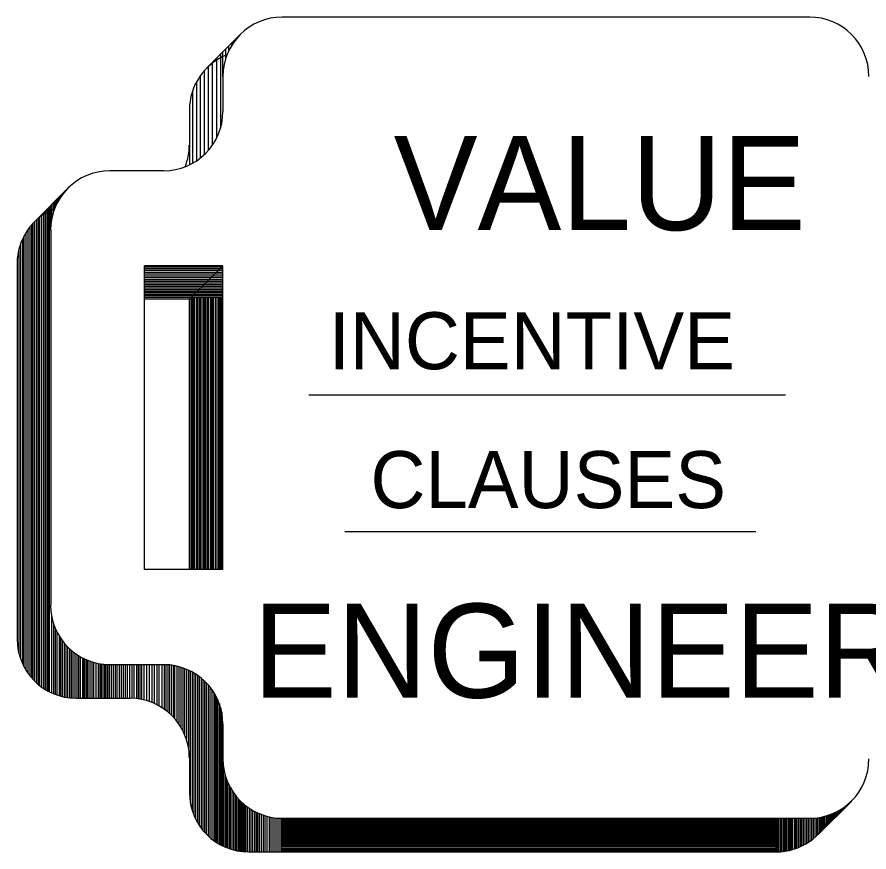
# Model space of a CAD drawing. Extents: x 22339.2 to 22413.4, y 22369.6 to 22418.8.
# Drawn here: x 22357.866 to 22359.063, y 22371.331 to 22372.503 of the extents above; entities that cross this region are included whole.
import ezdxf

# ---------------------------------------------------------------- set-up
doc = ezdxf.new("R2010")
doc.units = 0
doc.layers.add('Level 2', color=7, linetype='Continuous')
doc.layers.add('Level 7', color=7, linetype='Continuous')

msp = doc.modelspace()

# ---------------------------------------------------------------- linework, layer by layer
at = {"layer": 'Level 2'}
for p, q in [((22358.1327, 22372.432), (22358.1799, 22372.4792)), ((22358.1681, 22372.464), (22358.1681, 22372.4673)), ((22358.1716, 22372.4693), (22358.1716, 22372.4708)), ((22358.1556, 22372.4202), (22358.1556, 22372.4548)), ((22358.1596, 22372.4457), (22358.1596, 22372.4588)), ((22358.1639, 22372.4565), (22358.1639, 22372.4632)), ((22358.1466, 22372.4458), (22358.1466, 22372.3333)), ((22358.1522, 22372.4515), (22358.1522, 22372.3477)), ((22358.1349, 22372.4342), (22358.1349, 22372.316)), ((22358.1406, 22372.4398), (22358.1406, 22372.3233)), ((22358.1237, 22372.4212), (22358.1237, 22372.3055)), ((22358.1294, 22372.4283), (22358.1294, 22372.3103)), ((22358.1186, 22372.4128), (22358.1186, 22372.3017)), ((22358.1129, 22372.4), (22358.1129, 22372.2983)), ((22358.1084, 22372.373), (22358.1084, 22372.296)), ((22357.8907, 22372.2162), (22357.9379, 22372.2633)), ((22357.9244, 22372.2455), (22357.9244, 22372.2498)), ((22357.9261, 22372.2482), (22357.9261, 22372.2515)), ((22357.9277, 22372.2508), (22357.9277, 22372.2532)), ((22357.9294, 22372.2532), (22357.9294, 22372.2548)), ((22357.9117, 22372.2372), (22357.9117, 22371.5563)), ((22357.9136, 22372.2043), (22357.9136, 22372.239)), ((22357.9154, 22372.2217), (22357.9154, 22372.2408)), ((22357.9177, 22372.2303), (22357.9177, 22372.2432)), ((22357.9196, 22372.2353), (22357.9196, 22372.245)), ((22357.9212, 22372.2392), (22357.9212, 22372.2467)), ((22357.9227, 22372.2423), (22357.9227, 22372.2482)), ((22357.9007, 22372.2262), (22357.9007, 22371.5632)), ((22357.9036, 22372.229), (22357.9036, 22371.5612)), ((22357.9059, 22372.2313), (22357.9059, 22371.5597)), ((22357.9081, 22372.2335), (22357.9081, 22371.5583)), ((22357.9102, 22372.2357), (22357.9102, 22371.5572)), ((22357.8887, 22372.214), (22357.8887, 22371.5737)), ((22357.8911, 22372.2163), (22357.8911, 22371.5713)), ((22357.8939, 22372.2193), (22357.8939, 22371.5687)), ((22357.8959, 22372.2213), (22357.8959, 22371.5668)), ((22357.8981, 22372.2235), (22357.8981, 22371.5652)), ((22357.8814, 22372.2048), (22357.8814, 22371.5828)), ((22357.8842, 22372.2087), (22357.8842, 22371.579)), ((22357.8866, 22372.2115), (22357.8866, 22371.5762)), ((22357.8739, 22372.1917), (22357.8739, 22371.596)), ((22357.8761, 22372.1962), (22357.8761, 22371.5915)), ((22357.8787, 22372.2008), (22357.8787, 22371.5868)), ((22357.8712, 22372.1852), (22357.8712, 22371.6025)), ((22357.8687, 22372.1767), (22357.8687, 22371.611)), ((22357.8664, 22372.1572), (22357.8664, 22371.6305)), ((22358.1556, 22372.1543), (22358.1084, 22372.1072)), ((22358.1556, 22372.1522), (22358.0452, 22372.1522)), ((22358.1556, 22372.15), (22358.0452, 22372.15)), ((22358.1556, 22372.1475), (22358.0452, 22372.1475)), ((22358.1556, 22372.145), (22358.0452, 22372.145)), ((22358.1556, 22372.1423), (22358.0452, 22372.1423)), ((22358.1556, 22372.1398), (22358.0452, 22372.1398)), ((22358.1556, 22372.1373), (22358.0452, 22372.1373)), ((22358.1556, 22372.1347), (22358.0452, 22372.1347)), ((22358.1556, 22372.1323), (22358.0452, 22372.1323)), ((22358.1556, 22372.1298), (22358.0452, 22372.1298)), ((22358.1556, 22372.1273), (22358.0452, 22372.1273)), ((22358.1556, 22372.125), (22358.0452, 22372.125)), ((22358.1556, 22372.1227), (22358.0452, 22372.1227)), ((22358.1556, 22372.1207), (22358.0452, 22372.1207)), ((22358.1556, 22372.1182), (22358.0452, 22372.1182)), ((22358.1556, 22372.1162), (22358.0452, 22372.1162)), ((22358.1556, 22372.114), (22358.0452, 22372.114)), ((22358.1556, 22372.112), (22358.0452, 22372.112)), ((22358.1556, 22372.1095), (22358.0452, 22372.1095)), ((22358.1084, 22372.1072), (22358.0452, 22372.1072)), ((22358.1084, 22371.7277), (22358.1084, 22372.1072)), ((22358.1107, 22371.7277), (22358.1107, 22372.1095)), ((22358.1126, 22371.7277), (22358.1126, 22372.1095)), ((22358.1146, 22371.7277), (22358.1146, 22372.1095)), ((22358.1162, 22371.7277), (22358.1162, 22372.1095)), ((22358.1187, 22371.7277), (22358.1187, 22372.1095)), ((22358.1209, 22371.7277), (22358.1209, 22372.1095)), ((22358.1232, 22371.7277), (22358.1232, 22372.1095)), ((22358.1249, 22371.7277), (22358.1249, 22372.1095)), ((22358.1276, 22371.7277), (22358.1276, 22372.1095)), ((22358.1297, 22371.7277), (22358.1297, 22372.1095)), ((22358.1316, 22371.7277), (22358.1316, 22372.1095)), ((22358.1337, 22371.7277), (22358.1337, 22372.1095)), ((22358.1359, 22371.7277), (22358.1359, 22372.1095)), ((22358.1384, 22371.7277), (22358.1384, 22372.1095)), ((22358.1404, 22371.7277), (22358.1404, 22372.1095)), ((22358.1424, 22371.7277), (22358.1424, 22372.1095)), ((22358.1449, 22371.7277), (22358.1449, 22372.1095)), ((22358.1474, 22371.7277), (22358.1474, 22372.1095)), ((22358.1499, 22371.7277), (22358.1499, 22372.1095)), ((22358.1516, 22371.7277), (22358.1516, 22372.1095)), ((22358.1537, 22371.7277), (22358.1537, 22372.1095)), ((22357.9147, 22371.6638), (22357.9147, 22371.5548)), ((22357.9174, 22371.6527), (22357.9174, 22371.5537)), ((22357.9199, 22371.6458), (22357.9199, 22371.5527)), ((22357.9224, 22371.6403), (22357.9224, 22371.5518)), ((22357.9254, 22371.6348), (22357.9254, 22371.5508)), ((22357.9276, 22371.6315), (22357.9276, 22371.5502)), ((22357.9297, 22371.6283), (22357.9297, 22371.5497)), ((22357.9326, 22371.6247), (22357.9326, 22371.549)), ((22357.9349, 22371.622), (22357.9349, 22371.5485)), ((22357.9374, 22371.6193), (22357.9374, 22371.5482)), ((22357.9399, 22371.6168), (22357.9399, 22371.5477)), ((22357.9424, 22371.6147), (22357.9424, 22371.5475)), ((22357.9447, 22371.6127), (22357.9447, 22371.5473)), ((22357.9476, 22371.6105), (22357.9476, 22371.5472)), ((22357.9501, 22371.6087), (22357.9501, 22371.5472)), ((22357.9526, 22371.6072), (22357.9526, 22371.5472)), ((22357.9551, 22371.6057), (22357.9551, 22371.5472)), ((22357.9581, 22371.604), (22357.9581, 22371.5472)), ((22357.9602, 22371.6028), (22357.9602, 22371.5472)), ((22357.9616, 22371.6022), (22357.9616, 22371.5472)), ((22357.9637, 22371.6012), (22357.9637, 22371.5472)), ((22357.9659, 22371.6003), (22357.9659, 22371.5472)), ((22357.9686, 22371.5993), (22357.9686, 22371.5472)), ((22357.9712, 22371.5983), (22357.9712, 22371.5472)), ((22357.9737, 22371.5977), (22357.9737, 22371.5472)), ((22357.9771, 22371.5967), (22357.9771, 22371.5472)), ((22357.9801, 22371.596), (22357.9801, 22371.5472)), ((22357.9826, 22371.5955), (22357.9826, 22371.5472)), ((22357.9844, 22371.5953), (22357.9844, 22371.5472)), ((22357.9869, 22371.595), (22357.9869, 22371.5472)), ((22357.9891, 22371.5947), (22357.9891, 22371.5472)), ((22357.9909, 22371.5945), (22357.9909, 22371.5472)), ((22357.9932, 22371.5943), (22357.9932, 22371.5472)), ((22357.9959, 22371.5943), (22357.9959, 22371.5472)), ((22357.9984, 22371.5943), (22357.9984, 22371.5472)), ((22358.0012, 22371.5943), (22358.0012, 22371.5472)), ((22358.0041, 22371.5943), (22358.0041, 22371.5472)), ((22358.0066, 22371.5943), (22358.0066, 22371.5472)), ((22358.0099, 22371.5943), (22358.0099, 22371.5472)), ((22358.0127, 22371.5943), (22358.0127, 22371.5472)), ((22358.0152, 22371.5943), (22358.0152, 22371.5472)), ((22358.0181, 22371.5943), (22358.0181, 22371.5472)), ((22358.0212, 22371.5943), (22358.0212, 22371.5472)), ((22358.0242, 22371.5943), (22358.0242, 22371.5472)), ((22358.0274, 22371.5943), (22358.0274, 22371.5472)), ((22358.0306, 22371.5943), (22358.0306, 22371.5472)), ((22358.0342, 22371.5943), (22358.0342, 22371.5467)), ((22358.0367, 22371.5943), (22358.0367, 22371.5463)), ((22358.0389, 22371.5943), (22358.0389, 22371.546)), ((22358.0411, 22371.5943), (22358.0411, 22371.5457)), ((22358.0446, 22371.5943), (22358.0446, 22371.5448)), ((22358.0482, 22371.5943), (22358.0482, 22371.5438)), ((22358.0521, 22371.5943), (22358.0521, 22371.5427)), ((22358.0557, 22371.5943), (22358.0557, 22371.5413)), ((22358.0589, 22371.5943), (22358.0589, 22371.54)), ((22358.0626, 22371.5943), (22358.0626, 22371.5383)), ((22358.0654, 22371.5943), (22358.0654, 22371.5368)), ((22358.0697, 22371.5943), (22358.0697, 22371.5342)), ((22358.0732, 22371.5943), (22358.0732, 22371.5318)), ((22358.0751, 22371.5943), (22358.0751, 22371.5305)), ((22358.0782, 22371.5943), (22358.0782, 22371.528)), ((22358.0807, 22371.5938), (22358.0807, 22371.5258)), ((22358.0834, 22371.5935), (22358.0834, 22371.5233)), ((22358.0859, 22371.5932), (22358.0859, 22371.5208)), ((22358.0877, 22371.5928), (22358.0877, 22371.5188)), ((22358.0906, 22371.5923), (22358.0906, 22371.5153)), ((22358.0934, 22371.5917), (22358.0934, 22371.5115)), ((22358.0964, 22371.5908), (22358.0964, 22371.5068)), ((22358.0992, 22371.5898), (22358.0992, 22371.5018)), ((22358.1017, 22371.589), (22358.1017, 22371.4965)), ((22358.1044, 22371.5878), (22358.1044, 22371.4893)), ((22358.1072, 22371.5867), (22358.1072, 22371.4777)), ((22358.1094, 22371.5857), (22358.1094, 22371.4018)), ((22358.1121, 22371.5842), (22358.1121, 22371.3902)), ((22358.1147, 22371.5827), (22358.1147, 22371.3828)), ((22358.1172, 22371.5812), (22358.1172, 22371.3773)), ((22358.1197, 22371.5795), (22358.1197, 22371.3727)), ((22358.1222, 22371.5777), (22358.1222, 22371.3687)), ((22358.1251, 22371.5755), (22358.1251, 22371.3647)), ((22358.1272, 22371.5737), (22358.1272, 22371.3618)), ((22358.1297, 22371.5713), (22358.1297, 22371.359)), ((22358.1319, 22371.5692), (22358.1319, 22371.3567)), ((22358.1346, 22371.5663), (22358.1346, 22371.354)), ((22358.1371, 22371.5633), (22358.1371, 22371.3518)), ((22358.1399, 22371.5597), (22358.1399, 22371.3493)), ((22358.1426, 22371.5557), (22358.1426, 22371.3473)), ((22357.9497, 22371.5472), (22358.0251, 22371.5472)), ((22358.1447, 22371.5522), (22358.1447, 22371.3458)), ((22358.1467, 22371.5483), (22358.1467, 22371.3445)), ((22358.1484, 22371.5448), (22358.1484, 22371.3435)), ((22358.1506, 22371.5395), (22358.1506, 22371.3422)), ((22358.1524, 22371.5338), (22358.1524, 22371.3412)), ((22358.1539, 22371.5275), (22358.1539, 22371.3403)), ((22358.1084, 22371.4638), (22358.1084, 22371.4147)), ((22358.1557, 22371.4565), (22358.1557, 22371.3395)), ((22358.1581, 22371.4415), (22358.1581, 22371.3385)), ((22358.1602, 22371.4343), (22358.1602, 22371.3375)), ((22358.1621, 22371.4295), (22358.1621, 22371.3368)), ((22358.1641, 22371.4252), (22358.1641, 22371.336)), ((22358.1657, 22371.422), (22358.1657, 22371.3355)), ((22358.1681, 22371.418), (22358.1681, 22371.3348)), ((22358.1702, 22371.4147), (22358.1702, 22371.3342)), ((22358.1726, 22371.4113), (22358.1726, 22371.3335)), ((22358.1742, 22371.4093), (22358.1742, 22371.3332)), ((22358.1766, 22371.4065), (22358.1766, 22371.3327)), ((22358.1779, 22371.405), (22358.1779, 22371.3325)), ((22358.1797, 22371.4032), (22358.1797, 22371.3322)), ((22358.1817, 22371.4012), (22358.1817, 22371.332)), ((22358.1832, 22371.3998), (22358.1832, 22371.3318)), ((22358.9914, 22371.3557), (22359.0386, 22371.4028)), ((22358.1842, 22371.399), (22358.1842, 22371.3317)), ((22358.1854, 22371.398), (22358.1854, 22371.3315)), ((22358.1872, 22371.3965), (22358.1872, 22371.3315)), ((22358.1896, 22371.3947), (22358.1896, 22371.3315)), ((22358.1922, 22371.3928), (22358.1922, 22371.3315)), ((22358.1946, 22371.3913), (22358.1946, 22371.3315)), ((22358.1972, 22371.3897), (22358.1972, 22371.3315)), ((22358.1997, 22371.3883), (22358.1997, 22371.3315)), ((22359.0187, 22371.383), (22359.0187, 22371.3883)), ((22359.0202, 22371.3845), (22359.0202, 22371.3892)), ((22359.0217, 22371.386), (22359.0217, 22371.39)), ((22359.0234, 22371.3877), (22359.0234, 22371.391)), ((22359.0251, 22371.3893), (22359.0251, 22371.392)), ((22359.0266, 22371.3908), (22359.0266, 22371.393)), ((22359.0281, 22371.3923), (22359.0281, 22371.394)), ((22359.0296, 22371.3938), (22359.0296, 22371.3952)), ((22358.2022, 22371.387), (22358.2022, 22371.3315)), ((22358.2042, 22371.386), (22358.2042, 22371.3315)), ((22358.2066, 22371.385), (22358.2066, 22371.3315)), ((22358.2092, 22371.384), (22358.2092, 22371.3315)), ((22358.2119, 22371.383), (22358.2119, 22371.3315)), ((22358.2146, 22371.3822), (22358.2146, 22371.3315)), ((22358.2174, 22371.3813), (22358.2174, 22371.3315)), ((22358.2204, 22371.3805), (22358.2204, 22371.3315)), ((22358.2227, 22371.38), (22358.2227, 22371.3315)), ((22358.2257, 22371.3795), (22358.2257, 22371.3315)), ((22358.2284, 22371.3792), (22358.2284, 22371.3315)), ((22358.2311, 22371.3788), (22358.2311, 22371.3315)), ((22358.2342, 22371.3787), (22358.2342, 22371.3315)), ((22358.2369, 22371.3785), (22358.2369, 22371.3315)), ((22358.2369, 22371.3773), (22358.9324, 22371.3773)), ((22358.2369, 22371.3765), (22358.9324, 22371.3765)), ((22358.2369, 22371.3757), (22358.9324, 22371.3757)), ((22358.9324, 22371.3313), (22358.9324, 22371.3785)), ((22358.9342, 22371.3313), (22358.9342, 22371.3785)), ((22358.9356, 22371.3313), (22358.9356, 22371.3785)), ((22358.9369, 22371.3315), (22358.9369, 22371.3785)), ((22358.9391, 22371.3317), (22358.9391, 22371.3785)), ((22358.9407, 22371.3318), (22358.9407, 22371.3785)), ((22358.9427, 22371.332), (22358.9427, 22371.3785)), ((22358.9444, 22371.3322), (22358.9444, 22371.3785)), ((22358.9462, 22371.3325), (22358.9462, 22371.3785)), ((22358.9477, 22371.3328), (22358.9477, 22371.3785)), ((22358.9497, 22371.3332), (22358.9497, 22371.3785)), ((22358.9516, 22371.3335), (22358.9516, 22371.3785)), ((22358.9534, 22371.334), (22358.9534, 22371.3785)), ((22358.9557, 22371.3347), (22358.9557, 22371.3785)), ((22358.9582, 22371.3355), (22358.9582, 22371.3785)), ((22358.9602, 22371.3362), (22358.9602, 22371.3785)), ((22358.9622, 22371.3368), (22358.9622, 22371.3785)), ((22358.9644, 22371.3377), (22358.9644, 22371.3785)), ((22358.9666, 22371.3387), (22358.9666, 22371.3785)), ((22358.9684, 22371.3395), (22358.9684, 22371.3785)), ((22358.9709, 22371.3408), (22358.9709, 22371.3785)), ((22358.9734, 22371.3422), (22358.9734, 22371.3785)), ((22358.9757, 22371.3435), (22358.9757, 22371.3785)), ((22358.9781, 22371.345), (22358.9781, 22371.3785)), ((22358.9804, 22371.3465), (22358.9804, 22371.3785)), ((22358.9826, 22371.3482), (22358.9826, 22371.3785)), ((22358.9849, 22371.35), (22358.9849, 22371.3785)), ((22358.9874, 22371.352), (22358.9874, 22371.3788)), ((22358.9897, 22371.3542), (22358.9897, 22371.3792)), ((22358.9917, 22371.356), (22358.9917, 22371.3793)), ((22358.9939, 22371.3582), (22358.9939, 22371.3797)), ((22358.9956, 22371.3598), (22358.9956, 22371.38)), ((22358.9976, 22371.3618), (22358.9976, 22371.3805)), ((22358.9992, 22371.3635), (22358.9992, 22371.3808)), ((22359.0011, 22371.3653), (22359.0011, 22371.3813)), ((22359.0031, 22371.3673), (22359.0031, 22371.3818)), ((22359.0044, 22371.3687), (22359.0044, 22371.3823)), ((22359.0061, 22371.3703), (22359.0061, 22371.3828)), ((22359.0076, 22371.3718), (22359.0076, 22371.3833)), ((22359.0092, 22371.3735), (22359.0092, 22371.384)), ((22359.0102, 22371.3745), (22359.0102, 22371.3843)), ((22359.0122, 22371.3765), (22359.0122, 22371.3852)), ((22359.0137, 22371.378), (22359.0137, 22371.3858)), ((22359.0154, 22371.3797), (22359.0154, 22371.3867)), ((22359.0172, 22371.3815), (22359.0172, 22371.3875)), ((22358.2369, 22371.3745), (22358.9324, 22371.3745)), ((22358.2369, 22371.3732), (22358.9324, 22371.3732)), ((22358.2369, 22371.3717), (22358.9324, 22371.3717)), ((22358.2369, 22371.3702), (22358.9324, 22371.3702)), ((22358.2369, 22371.3688), (22358.9324, 22371.3688)), ((22358.2369, 22371.3673), (22358.9324, 22371.3673)), ((22358.2369, 22371.3658), (22358.9324, 22371.3658)), ((22358.2369, 22371.3643), (22358.9324, 22371.3643)), ((22358.2369, 22371.3628), (22358.9324, 22371.3628)), ((22358.2369, 22371.3613), (22358.9324, 22371.3613)), ((22358.2369, 22371.36), (22358.9324, 22371.36)), ((22358.2369, 22371.3585), (22358.9324, 22371.3585)), ((22358.2369, 22371.3572), (22358.9324, 22371.3572)), ((22358.2369, 22371.3558), (22358.9324, 22371.3558)), ((22358.2369, 22371.3543), (22358.9324, 22371.3543)), ((22358.2369, 22371.3528), (22358.9324, 22371.3528)), ((22358.2369, 22371.3512), (22358.9324, 22371.3512)), ((22358.2369, 22371.3495), (22358.9324, 22371.3495)), ((22358.2369, 22371.3478), (22358.9324, 22371.3478)), ((22358.2369, 22371.3463), (22358.9324, 22371.3463)), ((22358.2369, 22371.3445), (22358.9324, 22371.3445)), ((22358.2369, 22371.3428), (22358.9324, 22371.3428)), ((22358.2369, 22371.341), (22358.9324, 22371.341)), ((22358.1917, 22371.3313), (22358.9324, 22371.3313)), ((22358.2369, 22371.3392), (22358.9324, 22371.3392)), ((22358.2369, 22371.3372), (22358.9324, 22371.3372)), ((22358.2369, 22371.3353), (22358.9324, 22371.3353)), ((22358.2369, 22371.3335), (22358.9324, 22371.3335))]:
    msp.add_line(p, q, dxfattribs=at)
for centre, start, end in [((22358.1917, 22372.3729), 111.4079, 180), ((22358.025, 22372.3238), 338.5921, 0), ((22357.9497, 22372.1571), 111.4079, 180), ((22357.9497, 22371.6304), 180, 270), ((22358.025, 22371.4638), 0, 90), ((22358.1917, 22371.4146), 180, 270), ((22358.9323, 22371.4146), 270, 338.5921)]:
    msp.add_arc(centre, 0.0833, start, end, dxfattribs=at)
at = {"layer": 'Level 7'}
for p, q in [((22358.9796, 22372.5035), (22358.2389, 22372.5035)), ((22358.1556, 22372.4202), (22358.1556, 22372.371)), ((22358.0722, 22372.2877), (22357.9969, 22372.2877)), ((22357.9136, 22372.2043), (22357.9136, 22371.6777)), ((22358.1556, 22372.1543), (22358.0452, 22372.1543)), ((22358.0452, 22371.7277), (22358.0452, 22372.1543)), ((22358.1556, 22371.7277), (22358.1556, 22372.1543)), ((22358.2764, 22371.9732), (22358.9456, 22371.9732)), ((22358.3267, 22371.7812), (22358.9042, 22371.7812)), ((22358.1556, 22371.7277), (22358.0452, 22371.7277)), ((22357.9969, 22371.5943), (22358.0722, 22371.5943)), ((22358.1556, 22371.511), (22358.1556, 22371.4618)), ((22358.2389, 22371.3785), (22358.9796, 22371.3785))]:
    msp.add_line(p, q, dxfattribs=at)
for centre, start, end in [((22358.2388, 22372.4201), 90, 180), ((22358.9795, 22372.4201), 0, 90), ((22358.0722, 22372.3709), 270, 0), ((22357.9968, 22372.2043), 90, 180), ((22357.9968, 22371.6776), 180, 270), ((22358.0722, 22371.5109), 0, 90), ((22358.2388, 22371.4618), 180, 270), ((22358.9795, 22371.4618), 270, 0)]:
    msp.add_arc(centre, 0.0833, start, end, dxfattribs=at)

# ---------------------------------------------------------------- texts
at = {"layer": 'Level 2'}
for s, height, p in [('VALUE', 0.13199, (22358.3954, 22372.2043)), ('INCENTIVE', 0.08, (22358.3041, 22372.009)), ('CLAUSES', 0.08, (22358.3627, 22371.814)), ('ENGINEERING', 0.13199, (22358.1977, 22371.5478))]:
    msp.add_text(s, height=height, dxfattribs=at).set_placement(p)

doc.saveas('drawing.dxf')
